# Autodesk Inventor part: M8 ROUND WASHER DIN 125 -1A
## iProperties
Created: 2006-02
Part Number: M8 ROUND WASHER DIN 125 -1A
Material: Steel, Mild
Description: M8 ROUND WASHER FOR ANGLES
Document SubType Name: Modeling
Standard: DIN 125
Designer: Andy Moles
Standards Organization: DIN
Language: en-US
Size Designation: A 8.4
Categories: <MemberInstance><Categories><Category DisplayName="Fasteners" InternalName="e4da775c-781d-43d5-af7c-5136215cf5a6" Mnemonic="FSTN"><Category DisplayName="Washers
Density: 7.86 g/cm^3
Author: Andy Moles
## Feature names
1. Body [Extrusion]
